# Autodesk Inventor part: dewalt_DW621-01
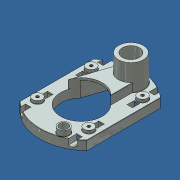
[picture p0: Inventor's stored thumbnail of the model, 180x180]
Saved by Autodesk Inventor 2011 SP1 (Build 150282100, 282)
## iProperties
Created: 2011-02
Part Number: dewalt_DW621-01
Material: 0.6025 GG-25 /  EN-GJL-250 / EN-JL1040
Catalog Web Link: www.mittelmeyer.de
Document SubType Name: Modellieren
Designer: TMT
Manufacturer: Standard
Standards Organization: Custom
Density: 1 g/cm^3
Author: TMT
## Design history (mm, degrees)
sketch "Skizze2"
  geometry: L1 (-55, 82)-(55, 82); L2 (55, 82)-(55, -82); L3 (55, -82)-(-55, -82); L4 (-55, -82)-(-55, 82); L5 (0, -114.8)-(0, 114.8) reference; L6 (-77, 0)-(77, 0) reference
  constraints: 8 end point, 2 parallel, 1 horizontal, 1 perpendicular, 2 other
  dimensions: "d4" = 164 distance of L3.end L1.start (= laenge_01); "d5" = 110 distance of L2.end L3.end (= breite_01)
extrude "Extrusion2" new body sketch "Skizze2" distance "d6" = 15 (= hoehe_01); taper "d7" = 0 deg
sketch "Skizze3"
  geometry: L1 (55, 82)-(55, -82) reference; L2 (-55, 82)-(55, 82) reference; L3 (-55, -82)-(-55, 82) reference; L4 (55, -82)-(-55, -82) reference; L5 (-111.65, 0)-(111.65, 0) reference; L6 (0, -114.8)-(0, 114.8) reference; L7 (-55, -60)-(-55, -82); L8 (-55, -82)-(55, -82); L9 (55, -82)-(55, -60); A1 r 79.75 centre (0, -2.25) between (55, -60) and (-55, -60); 1 further point
  constraints: 6 end point, 3 point on line, 2 collinear, 2 point on circle, 1 centre point, 1 perpendicular, 1 tangent
  dimensions: "d8" = 60 distance from line of L9.end L5
extrude "Extrusion3" cut sketch "Skizze3" stored distance "d9" = 21.5; taper "d10" = 0 deg
sketch "Skizze4"
  geometry: L1 (0, -114.8)-(0, 114.8) reference; L2 (-77, 0)-(77, 0) reference; C1 r 34 at (0, -14); A1 r 79.75 centre (0, -2.25) between (-55, -60) and (55, -60) reference; 2 further points
  constraints: 2 point on line, 1 centre point, 1 point on circle
  dimensions: "d11" = 68 distance of C1.centre point (0, -82); "d12" = 68 diameter of C1
extrude "Extrusion4" cut sketch "Skizze4" stored distance "d13" = 27; taper "d14" = 0 deg
sketch "Skizze5"
  geometry: L1 (0, -114.8)-(0, 114.8) reference; L2 (-77, 0)-(77, 0) reference; C1 r 34 at (0, -14) reference; C2 r 9 at (25, -68); 1 further point
  constraints: 1 centre point
  dimensions: "d15" = 25 distance from line of C2.centre L1; "d16" = 18 diameter of C2; "d17" = 54 vertical distance of C1.centre C2.centre
extrude "Extrusion5" join sketch "Skizze5" distance "d18" = 9; taper "d19" = 0 deg
sketch "Skizze6"
  geometry: L1 (0, -114.8)-(0, 114.8) reference; L2 (-77, 0)-(77, 0) reference; C1 r 8 at (-42, -44); C2 r 8 at (42, -44); C3 r 8 at (42, 44); C4 r 8 at (-42, 44); 1 further point
  constraints: 4 centre point, 3 equal radius, 4 other
  dimensions: "d20" = 16 diameter of C1; "d21" = 84 distance of C2.centre C1.centre; "d22" = 88 distance of C3.centre C2.centre
extrude "Extrusion6" join sketch "Skizze6" distance "d23" = 5; taper "d24" = 0 deg
mirror "Spiegeln1"
feature "Wandstärke1" dims "d71" = 3
sketch "Skizze7"
  geometry: L1 (0, -4.8)-(0, 28.8) reference; L2 (55, 15)-(-55, 15) reference; L3 (-55, 0)-(55, 0) reference; L4 (-55, 0)-(-55, 15) reference; L5 (55, 15)-(55, 0) reference; L6 (-37.5, 13)-(-46.5, 13); L7 (-46.5, 13)-(-46.5, 3); L8 (-46.5, 3)-(-37.5, 3); L9 (-37.5, 3)-(-37.5, 13); L10 (46.5, 13)-(37.5, 13); L11 (37.5, 13)-(37.5, 3); L12 (37.5, 3)-(46.5, 3); L13 (46.5, 3)-(46.5, 13); L14 (-42, 3)-(-46.5, 5.598); L15 (-42, 3)-(-37.5, 5.598); L16 (42, 3)-(46.5, 5.598); L17 (42, 3)-(37.5, 5.598); 1 further point
  constraints: 24 end point, 6 parallel, 4 point on line, 2 collinear, 2 horizontal, 2 midpoint, 2 perpendicular, 2 other
  dimensions: "d25" = 9 distance of L11.end L12.end; "d26" = 75 distance between parallel lines of L9 L11; "d27" = 12 distance between parallel lines of L8 L2; "d28" = 2 distance between parallel lines of L6 L2; "d43" = 30 deg angle of L8 L14; "d44" = 30 deg angle of L8 L15 (= d43)
extrude "Extrusion7" cut sketch "Skizze7" stored distance "d29" = 197.25; taper "d30" = 0 deg
sketch "Skizze8"
  geometry: L1 (-77, 0)-(77, 0) reference; L2 (0, -114.8)-(0, 114.8) reference; L3 (46.5, 46.179)-(46.5, 67.041) reference; L4 (37.5, 72.633)-(37.5, 46.179) reference; L5 (37.5, -59)-(46.5, -59); L6 (37.5, -35)-(46.5, -35); L7 (37.5, -23)-(46.5, -23); L8 (37.5, -46.179)-(37.5, -72.633) reference; L9 (46.5, -67.041)-(46.5, -46.179) reference; L10 (37.5, 41.821)-(37.5, -41.821) reference; L11 (46.5, -59)-(37.5, -59); L12 (37.5, -59)-(37.5, -72.633); L13 (37.5, -72.633)-(46.5, -72.633); L14 (46.5, -72.633)-(46.5, -59); L15 (46.5, -23)-(37.5, -23); L16 (37.5, -23)-(37.5, -35); L17 (37.5, -35)-(46.5, -35); L18 (46.5, -35)-(46.5, -23); L19 (46.5, -41.821)-(46.5, 41.821) reference; A1 r 79.75 centre (0, 2.25) between (46.5, 67.041) and (37.5, 72.633) reference; A2 r 79.75 centre (0, -2.25) between (37.5, -72.633) and (46.5, -67.041) reference; A3 r 5 centre (42, -44) between (37.5, -46.179) and (46.5, -46.179) reference; A4 r 5 centre (42, 44) between (46.5, 46.179) and (37.5, 46.179) reference; A5 r 5 centre (42, 44) between (37.5, 41.821) and (46.5, 41.821) reference; A6 r 5 centre (42, -44) between (46.5, -41.821) and (37.5, -41.821) reference; 1 further point
  constraints: 22 end point, 6 point on line, 5 perpendicular, 4 parallel, 2 horizontal
  dimensions: "d31" = 12 distance between parallel lines of L7 L6; "d32" = 35 distance between parallel lines of L1 L6; "d33" = 59 distance between parallel lines of L1 L5
  node "Projizierte Kontur1"
sketch "Skizze16"
  geometry: L1 (-37.5, 3)-(-37.5, 13) reference; L2 (-42, 3)-(-46.5, 5.598) reference; L3 (-46.5, 13)-(-46.5, 3) reference; L4 (46.5, 3)-(46.5, 13) reference; L5 (42, 3)-(46.5, 5.598) reference; L6 (42, 3)-(37.5, 5.598) reference; L7 (37.5, 13)-(37.5, 3) reference; L8 (37.5, 12)-(-37.5, 12) reference; L9 (52, 12)-(46.5, 12) reference; L10 (-46.5, 12)-(-52, 12) reference; L11 (-35.5, 3)-(-35.5, 13); L12 (-42, 3)-(-37.5, 5.598) reference; L13 (-35.5, 4.443)-(-42, 0.691); L14 (-42, 0.691)-(-48.5, 4.443); L15 (-48.5, 13)-(-48.5, 3); L16 (-35.5, 12)-(-37.5, 12); L17 (-37.5, 5.598)-(-42, 3); L18 (-46.5, 5.598)-(-46.5, 12); L19 (-46.5, 12)-(-48.5, 12); 1 further point
  constraints: 16 end point, 6 point on line, 3 parallel, 2 collinear
  dimensions: "d72" = 2 distance between parallel lines of L13 L12; "d73" = 2 distance between parallel lines of L1 L11; "d74" = 2 distance between parallel lines of L15 L3; "d75" = 2 distance between parallel lines of L14 L2
extrude "Extrusion12" join sketch "Skizze16" stored distance "d76" = 25; taper "d77" = 0 deg
sketch "Skizze17"
  geometry: L1 (42, 3)-(46.5, 5.598) reference; L2 (37.5, 5.598)-(42, 3) reference; L3 (37.5, 12)-(37.5, 5.598) reference; L4 (35.5, 12)-(37.5, 12) reference; L5 (35.5, 4.443)-(35.5, 12) reference; L6 (42, 0.691)-(35.5, 4.443) reference; L7 (48.5, 4.443)-(42, 0.691) reference; L8 (48.5, 12)-(48.5, 4.443) reference; L9 (46.5, 12)-(48.5, 12) reference; L10 (46.5, 5.598)-(46.5, 12) reference; 1 further point
extrude "Extrusion13" join sketch "Skizze17" stored distance "d78" = 25; taper "d79" = 0 deg
mirror "Spiegeln4"
fillet "Rundung3" dims "d80" = 2
fillet "Rundung4" dims "d81" = 2
extrude "Extrusion14" cut sketch "Skizze8" distance "d82" = 5.5; taper "d83" = 0 deg
sketch "Skizze18"
  geometry: L1 (71, -66.725)-(71, -20.857) reference; L2 (0, -20.857)-(0, -66.725) reference; L3 (-13, -58.162)-(-13, 65.305) reference; L4 (-16.5, 62.271)-(-16.5, -55.128) reference; L5 (-11, -19.428)-(-2, -19.428) reference; L6 (-2, 45.392)-(-2, -19.428) reference; L7 (-11, -55.428)-(-11, -42.608) reference; L8 (-2, -19.428)-(-11, -19.428); L9 (-11, 3.572)-(-2, 3.572); L10 (-11, -55.428)-(-2, -55.428) reference; L11 (-2, -31.428)-(-11, -31.428) reference; L12 (112.5, 3.572)-(-41.5, 3.572) reference; L13 (-11, -55.428)-(-2, -55.428); L14 (-2, -31.428)-(-11, -31.428); L15 (-13, -55.428)-(0, -55.428); L16 (0, -55.428)-(0, -31.428); L17 (0, -31.428)-(-13, -31.428); L18 (-13, -31.428)-(-13, -55.428); L19 (-13, -19.428)-(-0.389, -19.428); L20 (-13, 3.572)-(1.251, 3.572); L21 (-11, -55.428)-(-2, -55.428) reference; L22 (-2, -42.608)-(-2, -55.428) reference; L23 (-11, -19.428)-(-11, 45.392) reference; L24 (-2, -31.428)-(-11, -31.428) reference; L25 (-11, -38.249)-(-11, -31.428) reference; L26 (-2, -31.428)-(-2, -38.249) reference; C1 r 6 at (10.5, -64.428) reference; A1 r 37 centre (35.5, -10.428) between (0, -20.857) and (71, -20.857) reference; A2 r 76.75 centre (35.5, 1.322) between (0, -66.725) and (71, -66.725) reference; A3 r 76.75 centre (35.5, 5.822) between (-13, 65.305) and (-16.5, 62.271) reference; A4 r 76.75 centre (35.5, 1.322) between (-16.5, -55.128) and (-13, -58.162) reference; A5 r 5 centre (-6.5, 47.572) between (-11, 45.392) and (-2, 45.392) reference; A6 r 37 centre (35.5, -10.428) between (0, -20.857) and (-0.389, -19.428); A7 r 5 centre (-6.5, -40.428) between (-11, -42.608) and (-2, -42.608) reference; A8 r 5 centre (-6.5, -40.428) between (-2, -38.249) and (-11, -38.249) reference; 1 further point
  constraints: 20 end point, 6 point on line, 4 collinear, 4 parallel, 3 horizontal, 3 point on circle, 2 perpendicular, 1 centre point, 1 coincident, 1 midpoint
extrude "Extrusion15" cut sketch "Skizze18" stored distance "d84" = 15; taper "d85" = 0 deg
mirror "Spiegeln5"
sketch "Skizze19"
  geometry: L1 (7.557, 0)-(-3.753, 0); L2 (-3.753, 0)-(-3.753, 19.428); L3 (-3.753, 19.428)-(7.557, 19.428); L4 (7.557, 19.428)-(7.557, 0); L5 (-3.753, 19.428)-(-0.224, 19.428) reference; L6 (-3.753, 19.428)-(-3.753, 31.428) reference; 2 further points
  constraints: 8 end point, 2 collinear, 2 parallel, 1 horizontal, 1 perpendicular
extrude "Extrusion16" cut sketch "Skizze19" distance "d86" = 7; taper "d87" = 0 deg
mirror "Spiegeln7"
sketch "Skizze9"
  geometry: C1 r 8 at (0, 0) reference; 1 further point
hole "Hole1" sketch "Skizze9" at (0, 0) diameter "d36" = 4.917; stored, may be unused: countersink angle "d40" = 90 deg, drill point angle "d42" = 118 deg; dims "d37" = 6, "d38" = 4, "d39" = 2, "d41" = 8
mirror "Spiegeln2"
mirror "Spiegeln3"
sketch "Skizze10"
  geometry: L1 (55, 60)-(55, -60) reference; C1 r 34 at (0, -14) reference; C2 r 21 at (9, 58); 1 further point
  constraints: 1 centre point
  dimensions: "d45" = 42 diameter of C2; "d46" = 46 distance from line of C2.centre L1 (computed from d45); "d47" = 72 vertical distance of C1.centre C2.centre
extrude "Extrusion9" join sketch "Skizze10" distance "d48" = 42; taper "d49" = -1 deg
sketch "Skizze11"
  geometry: C1 r 20.267 at (0, 0) reference; 1 further point
hole "Hole2" sketch "Skizze11" at (0, 0) diameter "d50" = 28; stored, may be unused: countersink angle "d54" = 90 deg, drill point angle "d56" = 118 deg; dims "d51" = 6, "d52" = 4, "d53" = 2, "d55" = 8
sketch "Skizze12"
  geometry: C1 r 9 at (0, 0) reference; 1 further point
hole "Hole3" sketch "Skizze12" at (0, 0) diameter "d57" = 14; stored, may be unused: countersink angle "d61" = 90 deg, drill point angle "d63" = 118 deg; dims "d58" = 6, "d59" = 4, "d60" = 2, "d62" = 8
sketch "Skizze13"
  geometry: L1 (55, 60)-(55, -60) reference; L2 (37.5, -72.633)-(37.5, -59) reference; L3 (25, 45.56)-(25, 9.043); L4 (-20.774, 12.915)-(-37.503, 0.004); L5 (-32.33, -3.474)-(-10.271, 64.275); A1 r 21 centre (9, 58) between (25, 44.399) and (-11.034, 64.296) reference; A2 r 34 centre (0, -14) between (25, 9.043) and (-32.436, -3.807) reference; A3 r 20.267 centre (9, 58) between (-10.271, 64.275) and (25, 45.56) reference; 3 further points
  constraints: 8 point on circle, 6 end point, 3 tangent, 1 parallel, 1 point on line
  dimensions: "d64" = 30 distance between parallel lines of L1 L3
extrude "Extrusion10" join sketch "Skizze13" distance "d65" = 14; taper "d66" = 0 deg
sketch "Skizze14"
  geometry: L1 (32.33, -3.474)-(11.974, 59.044) reference; L2 (-25, 44.399)-(-25, 9.043) reference; L3 (29.477, -4.403)-(8.993, 58.511); L4 (-22, 45.55)-(-22, 9.043); L5 (29.477, -4.403)-(-22, 9.043); A1 r 21 centre (-9, 58) between (11.974, 59.044) and (-25, 44.399) reference; A2 r 18 centre (-9, 58) between (8.993, 58.511) and (-22, 45.55); 1 further point
  constraints: 6 end point, 2 point on circle, 1 centre point, 2 other
  dimensions: "d70" = 3 distance between parallel lines of L3 L1
extrude "Extrusion11" cut sketch "Skizze14" distance "d68" = 25; taper "d69" = 0 deg
fillet "Rundung5" dims "d88" = 0.5
fillet "Rundung6" dims "d89" = 0.5
fillet "Rundung7" dims "d90" = 0.5
sketch "Skizze20"
  geometry: L1 (-33.007, 14.511)-(-18.777, -29.196) reference; L2 (-64, -28.251)-(-64, 1.55) reference; L3 (-15.364, -32.319)-(-30.742, 14.913); L4 (-66.278, 0.667)-(-66.278, -30.079); A1 r 18 centre (-51, 14) between (-33.007, 14.511) and (-64, 1.55) reference; A2 r 20.278 centre (-51, 14) between (-30.742, 14.913) and (-66.278, 0.667); A3 r 37 centre (-42, -58) between (-64, -28.251) and (-77.889, -67) reference; A4 r 37 centre (-42, -58) between (-6.111, -67) and (-18.777, -29.196) reference; A5 r 76.75 centre (-42, -41.75) between (-6.5, 26.296) and (-77.5, 26.296) reference; 1 further point
  constraints: 4 end point, 4 point on circle, 1 centre point, 1 tangent
extrude "Extrusion17" join sketch "Skizze20" stored distance "d92" = 7; taper "d93" = 0 deg
node "Volumenkörper1"
node "Volumenkörpern"
node "Oberflächenkörpern"
node "Projizierte Kontur2"
node "Projizierte Kontur3"
node "Projizierte Kontur4"
other parameters: "laenge_01" = 164 [user parameter; used in 1 equation term], "breite_01" = 110 [user parameter; used in 1 equation term], "hoehe_01" = 15 [user parameter; used in 1 equation term]
